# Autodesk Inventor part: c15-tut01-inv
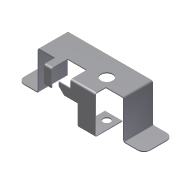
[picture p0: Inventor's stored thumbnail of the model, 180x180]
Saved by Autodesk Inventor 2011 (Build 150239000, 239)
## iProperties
Created: 2010-05
Part Number: c15-tut01-inv
Material: Default
Document SubType Name: Sheet Metal
Designer: CADSoft
Density: 1 g/cm^3
Flat Pattern Width: 11.2524 cm
Flat Pattern Length: 22.0048 cm
Flat Pattern Area: 247.606 cm^2
Sheet Metal Rule: Default_mm
Sheet Metal Width: 112.524 mm
Sheet Metal Length: 220.048 mm
Sheet Metal Area: 24760.634 mm^2
Author: CADSoft
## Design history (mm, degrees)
node "Face1"
  sketch "Sketch1"
    geometry: L1 (0, -18)-(-8, -18); L2 (-8, -18)-(-8, -6); L3 (-8, -6)-(-27, -6); L4 (-27, -6)-(-27, 26); L5 (-27, 26)-(68, 26); L6 (68, 26)-(68, -6); L7 (68, -6)-(48, -6); L8 (48, -6)-(48, -18); L9 (48, -18)-(21, -18); L10 (21, -18)-(21, 0); L11 (21, 0)-(0, 0); L12 (0, 0)-(0, -18); 1 further point
    constraints: 24 end point, 9 parallel, 1 coincident, 1 collinear, 1 horizontal, 1 perpendicular
    dimensions: "d0" = 95 distance of L4.end L5.end; "d1" = 26 distance between parallel lines of L5 L11; "d2" = 32 distance of L3.end L4.end; "d3" = 44 distance between parallel lines of L1 L5; "d4" = 19 distance of L2.end L3.end; "d5" = 8 distance of L1.start L1.end; "d6" = 27 distance of L8.end L9.end; "d7" = 20 distance of L6.end L7.end; "d8" = 32 distance of L5.end L6.end; "d9" = 44 distance between parallel lines of L9 L5
sketch "Sketch2"
  geometry: L1 (20, -41)-(42, -41); L2 (20, 0)-(0, 0) reference; L3 (20, 0)-(20, -41); 1 further point
  constraints: 4 end point, 1 perpendicular
  dimensions: "d13" = 22 distance of L1.start L1.end; "d37" = 41 distance between parallel lines of L1 L2
sketch "Sketch3"
  geometry: L1 (0, -41)-(-22, -41); L2 (19, 0)-(0, 0) reference; L3 (0, -41)-(0, 0); 1 further point
  constraints: 4 end point, 1 perpendicular
  dimensions: "d26" = 22 distance of L1.start L1.end; "d47" = 41 distance of L1.start L2.end
node "Contour Flange3"
node "Contour Flange4"
node "Contour Flange5"
  sketch "Sketch5"
    geometry: L1 (0, 12)-(-1, 12) reference; L2 (-1, 0)-(41, 0); L3 (41, 0)-(41, 30); 1 further point
    constraints: 4 end point, 1 parallel, 1 perpendicular
    dimensions: "d57" = 42 distance of L2.start L2.end; "d58" = 30 distance of L2.end L3.end
sketch "Sketch6"
  geometry: L1 (27, 38)-(27, 0) reference; L2 (-6.407, 21)-(8, 21); L3 (8, 21)-(8, -11.482); L4 (8, -11.482)-(-6.407, -11.482); L5 (-6.407, -11.482)-(-6.407, 21); L6 (0, 40)-(27, 40) reference; 1 further point
  constraints: 8 end point, 2 parallel, 1 horizontal, 1 perpendicular
  dimensions: "d69" = 19 distance between parallel lines of L2 L6; "d70" = 19 distance between parallel lines of L3 L1
cut "Cut1" sketch "Sketch6" dims "d71" = 1 (= Thickness), "d72" = 0
node "Face2"
  sketch "Sketch7"
    geometry: L1 (0, -17)-(-13, -17); L2 (-13, -17)-(-13, -7); L3 (-13, -7)-(0, -7); L4 (0, -7)-(0, -17); 1 further point
    constraints: 8 end point, 2 parallel, 1 horizontal, 1 perpendicular
    dimensions: "d73" = 13 distance of L2.end L3.end; "d74" = 10 distance of L1.end L2.end
feature "Corner Chamfer1" dims "d80" = 6, "d81" = 6, angle "d82" = 45 deg
node "Flange1"
feature "Corner Round1" dims "d93" = 7, "d94" = 7
hole "Hole1" diameter "d97" = 13; stored, may be unused: countersink angle "d101" = 90 deg, drill point angle "d103" = 118 deg; dims "d95" = 22, "d96" = 29, "d98" = 6, "d99" = 4, "d100" = 2, "d102" = 1 (= Thickness)
hole "Hole2" diameter "d106" = 8; stored, may be unused: countersink angle "d110" = 90 deg, drill point angle "d112" = 118 deg; dims "d104" = 22, "d105" = 29, "d107" = 6, "d108" = 4, "d109" = 2, "d111" = 1 (= Thickness)
body "Solid1"
face "Plate1" dims "Thickness" = 1 (derived)
face "Plate4" dims "d38" = 1 (= BendReliefWidth), "d39" = 0.5 (= BendReliefDepth), "d40" = 2 (= MinimumRemnant), "d41" = 1 (= BendRadius), "d42" = 1 (= BendRadius), "d43" = 1, "d44" = 4 (= CornerReliefSize), "d45" = 1 (= GapSize), "d46" = 1 (= JacobiRadiusSize), "SeamGap" = 0.01, "Thickness" = 1 (derived)
bend "Bend3" dims "d38" = 1 (= BendReliefWidth), "d39" = 0.5 (= BendReliefDepth), "d40" = 2 (= MinimumRemnant), "d41" = 1 (= BendRadius), "d42" = 1 (= BendRadius), "d43" = 1, "SeamGap" = 0.01, "Thickness" = 1 (derived)
feature "Corner3" dims "d43" = 1, "d44" = 4 (= CornerReliefSize), "d45" = 1 (= GapSize), "d46" = 1 (= JacobiRadiusSize)
face "Plate5" dims "d48" = 1 (= BendReliefWidth), "d49" = 0.5 (= BendReliefDepth), "d50" = 2 (= MinimumRemnant), "d51" = 1 (= BendRadius), "d52" = 1 (= BendRadius), "d53" = 1, "d54" = 4 (= CornerReliefSize), "d55" = 1 (= GapSize), "d56" = 1 (= JacobiRadiusSize), "SeamGap" = 0.01, "Thickness" = 1 (derived)
bend "Bend4" dims "d48" = 1 (= BendReliefWidth), "d49" = 0.5 (= BendReliefDepth), "d50" = 2 (= MinimumRemnant), "d51" = 1 (= BendRadius), "d52" = 1 (= BendRadius), "d53" = 1, "SeamGap" = 0.01, "Thickness" = 1 (derived)
feature "Corner4" dims "d53" = 1, "d54" = 4 (= CornerReliefSize), "d55" = 1 (= GapSize), "d56" = 1 (= JacobiRadiusSize)
face "Plate6" dims "d60" = 1 (= BendReliefWidth), "d61" = 0.5 (= BendReliefDepth), "d62" = 2 (= MinimumRemnant), "d63" = 1 (= BendRadius), "d64" = 1 (= BendRadius), "d65" = 1, "d66" = 4 (= CornerReliefSize), "d67" = 1 (= GapSize), "d68" = 1 (= JacobiRadiusSize), "SeamGap" = 0.01, "Thickness" = 1 (derived)
bend "Bend5" dims "d60" = 1 (= BendReliefWidth), "d61" = 0.5 (= BendReliefDepth), "d62" = 2 (= MinimumRemnant), "d63" = 1 (= BendRadius), "d64" = 1 (= BendRadius), "d65" = 1, "SeamGap" = 0.01, "Thickness" = 1 (derived)
feature "Corner5" dims "d65" = 1, "d66" = 4 (= CornerReliefSize), "d67" = 1 (= GapSize), "d68" = 1 (= JacobiRadiusSize)
face "Plate7" dims "d75" = 1 (= BendRadius), "d76" = 1 (= BendReliefWidth), "d78" = 2 (= MinimumRemnant), "Thickness" = 1 (derived)
bend "Bend6" dims "d75" = 1 (= BendRadius), "d76" = 1 (= BendReliefWidth), "d77" = 0.5 (= BendReliefDepth), "d78" = 2 (= MinimumRemnant), "d79" = 1 (= BendRadius), "SeamGap" = 0.01, "Thickness" = 1 (derived)
sketch "Sketch8"
  geometry: L1 (0, 19)-(-8, 19); L2 (-8, 19)-(-8, 0); 2 other entities
  constraints: 4 end point, 4 other
face "Plate8" dims "d83" = 1 (= BendReliefWidth), "d84" = 0.5 (= BendReliefDepth), "d85" = 2 (= MinimumRemnant), "d86" = 1 (= BendRadius), "d87" = 19, "d88" = 90 deg, "d89" = 1 (= BendRadius), "d90" = 4 (= CornerReliefSize), "d91" = 1 (= GapSize), "d92" = 1 (= JacobiRadiusSize), "SeamGap" = 0.01, "Thickness" = 1 (derived)
bend "Bend7" dims "d83" = 1 (= BendReliefWidth), "d84" = 0.5 (= BendReliefDepth), "d85" = 2 (= MinimumRemnant), "d86" = 1 (= BendRadius), "d87" = 19, "d88" = 90 deg, "d89" = 1 (= BendRadius), "SeamGap" = 0.01, "Thickness" = 1 (derived)
feature "Corner6" dims "d87" = 19, "d88" = 90 deg, "d90" = 4 (= CornerReliefSize), "d91" = 1 (= GapSize), "d92" = 1 (= JacobiRadiusSize)
feature "Definition1"
other parameters: "BendRadius" = 1 (= Thickness), "BendReliefWidth" = 1 (= Thickness), "BendReliefDepth" = 0.5 (= 0.5 x Thickness), "CornerReliefSize" = 4 (= 4 x Thickness), "MinimumRemnant" = 2 (= 2 x Thickness), "TransitionRadius" = 1 (= BendRadius), "JacobiRadiusSize" = 1 (= BendRadius), "GapSize" = 1 (= Thickness), "d10" = 1 (= BendRadius), "BendRadius" = 1, "BendReliefDepth" = 0.5, "BendReliefWidth" = 1, "CornerReliefSize" = 4, "GapSize" = 1, "JacobiRadiusSize" = 1, "MinimumRemnant" = 2, "Thickness" = 1, "TransitionRadius" = 1
